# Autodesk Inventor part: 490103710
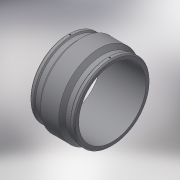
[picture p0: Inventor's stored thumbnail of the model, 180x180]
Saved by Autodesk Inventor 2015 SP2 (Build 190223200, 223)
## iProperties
Created: 2017-06
Part Number: 490103710
Material: Generic
Description: PLASSON COUPLER 710
Document SubType Name: Modeling
Designer: KIM
Mass: 61056.5 g
Surface Area: 25505.4 cm^2
Volume: 61056.5 cm^3
Density: 1 g/cm^3
Appearance: Default
Author: KIM
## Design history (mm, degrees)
derived "490103.ipt"
feature "Solid1::490103.ipt"
tag "TaggingFeature1"
body "Solid1"
other parameters: "d13" = 472, "d15" = 236, "d16" = 236, "d23" = 853, "d24" = 776, "d25" = 135 deg, "d26" = 188.8, "d27" = 135 deg, "d35" = 15, "d39" = 0, "d40" = 4, "d41" = 14, "d42" = 0, "d43" = 135 deg, "d44" = 51.92, "d46" = 6, "d47" = 0, "L_" = 472, "L_1" = 236, "D_" = 853, "d_2" = 12
